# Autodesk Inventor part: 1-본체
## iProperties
Created: 2015-05
Part Number: 1-본체
Document SubType Name: Modeling
Designer: elite
Density: 1.06 g/cm^3
Material: ABS 플라스틱
Mass: 32.0338 g
Surface Area: 305.458 cm^2
Volume: 30.2206 cm^3
Author: elite
